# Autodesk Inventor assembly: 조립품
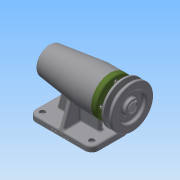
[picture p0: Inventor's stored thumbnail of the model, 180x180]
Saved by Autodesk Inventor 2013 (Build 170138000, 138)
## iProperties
Created: 2018-09
Part Number: 조립품
Document SubType Name: Assembly
Designer: Administrator
Author: Administrator
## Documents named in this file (12)
- C:\Users\Administrator\Desktop\480908V1010\조립품.iam
- C:\Users\Administrator\Desktop\480908V1010\본체.ipt
- C:\Users\Administrator\Desktop\480908V1010\축.ipt
- C:\Users\Administrator\Desktop\480908V1010\베어링 6004.ipt
- C:\Users\Administrator\Desktop\480908V1010\어댑터슬리브.ipt
- C:\Users\Administrator\Desktop\480908V1010\볼트 M4.ipt
- C:\Users\Administrator\Desktop\480908V1010\베어링 51202.ipt
- C:\Users\Administrator\Desktop\480908V1010\커버.ipt
- C:\Users\Administrator\Desktop\480908V1010\오일 실.ipt
- C:\Users\Administrator\Desktop\480908V1010\멈춤나사 M3.ipt
- C:\Users\Administrator\Desktop\480908V1010\키 5 x 5 x 16.ipt
- C:\Users\Administrator\Desktop\480908V1010\V벨트풀리.ipt
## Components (1 placed, 1 different names)
1. V벨트풀리:1
